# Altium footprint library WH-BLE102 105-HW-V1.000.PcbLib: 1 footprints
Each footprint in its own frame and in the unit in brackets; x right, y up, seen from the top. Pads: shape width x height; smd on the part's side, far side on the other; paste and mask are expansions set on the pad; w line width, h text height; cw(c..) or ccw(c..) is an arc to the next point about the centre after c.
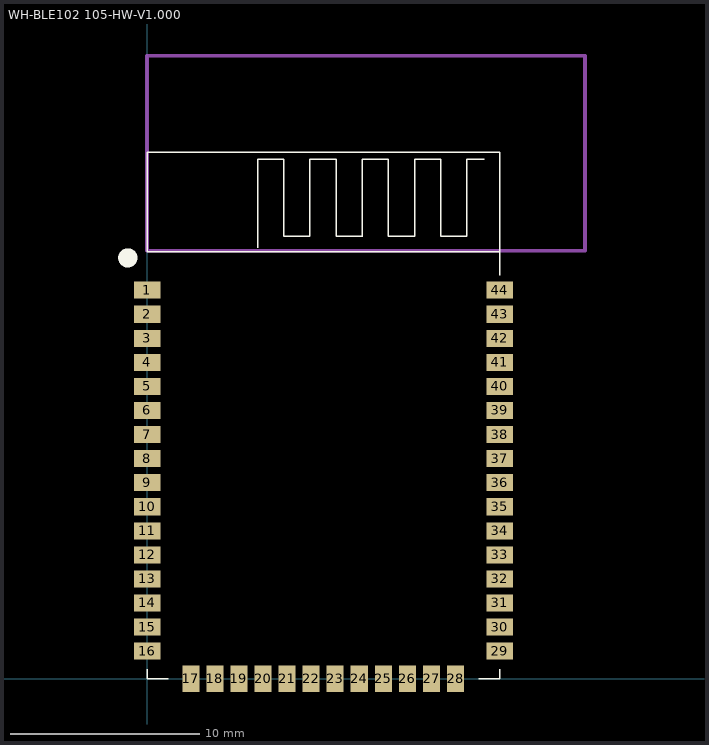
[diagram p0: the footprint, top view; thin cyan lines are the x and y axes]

## WH-BLE102 105-HW-V1.000 [mm]
pads (44):
  rect 1.4x0.9 smd: 1(0,20.52) 2(0,19.25) 3(0,17.98) 4(0,16.71) 5(0,15.44) 6(0,14.17) 7(0,12.9) 8(0,11.63) 9(0,10.36) 10(0,9.09) 11(0,7.82) 12(0,6.55) 13(0,5.28) 14(0,4.01) 15(0,2.74) 16(0,1.47) 29(18.62,1.47) 30(18.62,2.74) 31(18.62,4.01) 32(18.62,5.28) 33(18.62,6.55) 34(18.62,7.82) 35(18.62,9.09) 36(18.62,10.36) 37(18.62,11.63) 38(18.62,12.9) 39(18.62,14.17) 40(18.62,15.44) 41(18.62,16.71) 42(18.62,17.98) 43(18.62,19.25) 44(18.62,20.52)
  rect 0.9x1.4 smd: 17(2.31,0) 18(3.58,0) 19(4.85,0) 20(6.12,0) 21(7.39,0) 22(8.66,0) 23(9.93,0) 24(11.2,0) 25(12.47,0) 26(13.74,0) 27(15.02,0) 28(16.29,0)
Top Overlay:
  circle w0.508: c-1.016,22.225 r0.254
  lines w0.07: 0,0.5 0,0 1.12,0 ; 5.836,22.76 5.836,23.36 5.836,27.43 ; 5.836,27.42 7.206,27.42 ; 7.216,23.37 7.216,27.43 7.216,23.36 8.596,23.36 8.596,27.43 ; 8.596,23.37 8.596,27.43 ; 9.976,23.37 9.976,27.43 ; 11.346,23.36 9.976,23.36 9.976,27.43 ; 11.356,23.35 11.356,27.42 ; 11.356,23.37 11.356,27.43 12.726,27.43 ; 12.736,23.37 14.116,23.37 14.116,27.43 14.116,23.36 ; 12.736,27.42 12.736,23.36 12.736,27.43 ; 14.116,27.42 15.496,27.42 ; 15.496,23.36 15.496,27.43 ; 16.876,27.42 17.796,27.42 ; 16.876,27.43 16.876,23.37 15.496,23.37 ; 17.5,0 18.62,0 18.62,0.5 ; 18.62,21.31 18.62,23.07 ; 18.62,21.5 18.62,27.813 0,27.813 0,22.55 18.62,22.55 ; 8.596,27.43 9.976,27.43 ; 15.496,23.37 15.496,27.43 ; 15.496,23.37 15.496,27.43
Mechanical 6:
  lines w0.203: 0,22.606 0,32.893 23.114,32.893 23.114,22.606 0,22.606
  text "Polygon Pour cutout" at 1.651,28.956 h1.02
